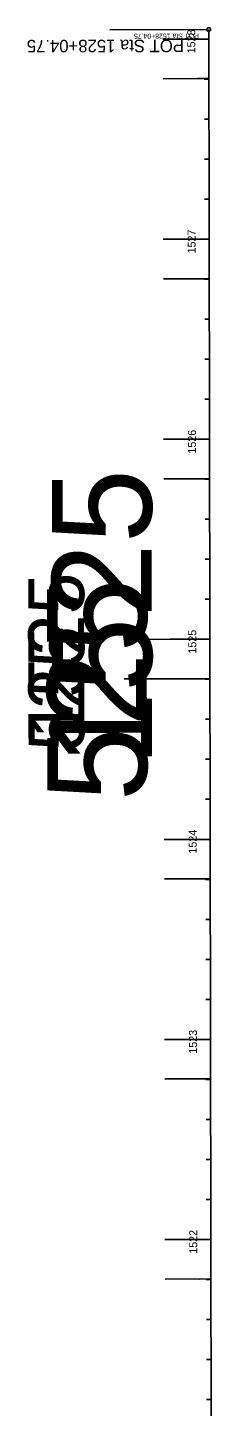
# Model space of a CAD drawing. Extents: x 448091 to 665917, y 1461380 to 1587607.
# Drawn here: x 450278 to 450373, y 1506458 to 1507147 of the extents above; entities that cross this region are included whole.
import ezdxf

# ---------------------------------------------------------------- set-up
doc = ezdxf.new("R2010")
doc.units = 0
for name, color, linetype in [('AttenuatorTM', 7, 'Continuous'), ('ATVHP', 7, 'Continuous'), ('Default', 7, 'Continuous'), ('TextShtNo', 7, 'Continuous'), ('TextTitle', 7, 'Continuous')]:
    doc.layers.add(name, color=color, linetype=linetype)

msp = doc.modelspace()

# ---------------------------------------------------------------- linework, layer by layer
at = {"layer": 'ATVHP'}
for p, q in [((450373.15, 1504839.62), (450369.29, 1507146.05)), ((450369.33, 1507121.54), (450363.58, 1507121.53)), ((450369.5, 1507021.54), (450363.75, 1507021.53)), ((450369.67, 1506921.54), (450363.92, 1506921.53)), ((450369.83, 1506821.54), (450349.08, 1506821.51)), ((450370, 1506721.54), (450364.25, 1506721.53)), ((450370.17, 1506621.54), (450364.42, 1506621.53)), ((450370.34, 1506521.54), (450364.59, 1506521.53))]:
    msp.add_line(p, q, dxfattribs=at)
at = {"layer": 'Default'}
for p, q in [((450368.29, 1507146.05), (450319.69, 1507145.97)), ((450369.3, 1507141.3), (450346.3, 1507141.26)), ((450369.3, 1507141.3), (450365, 1507141.29)), ((450369.33, 1507121.54), (450346.33, 1507121.5)), ((450369.33, 1507121.3), (450367.03, 1507121.3)), ((450369.37, 1507101.3), (450367.07, 1507101.3)), ((450369.4, 1507081.3), (450367.1, 1507081.3)), ((450369.43, 1507061.3), (450367.13, 1507061.3)), ((450369.47, 1507041.3), (450346.47, 1507041.26)), ((450369.47, 1507041.3), (450365.17, 1507041.29)), ((450369.5, 1507021.54), (450346.5, 1507021.5)), ((450369.5, 1507021.3), (450367.2, 1507021.3)), ((450369.53, 1507001.3), (450367.23, 1507001.3)), ((450369.57, 1506981.3), (450367.27, 1506981.3)), ((450369.6, 1506961.3), (450367.3, 1506961.3)), ((450369.63, 1506941.3), (450346.63, 1506941.26)), ((450369.63, 1506941.3), (450365.33, 1506941.29)), ((450369.67, 1506921.54), (450346.67, 1506921.5)), ((450369.67, 1506921.3), (450367.37, 1506921.3)), ((450369.7, 1506901.3), (450367.4, 1506901.3)), ((450369.73, 1506881.3), (450367.43, 1506881.3)), ((450369.77, 1506861.3), (450367.47, 1506861.3)), ((450369.8, 1506841.3), (450326.8, 1506841.23)), ((450369.8, 1506841.3), (450365.5, 1506841.29)), ((450369.83, 1506821.54), (450326.83, 1506821.47)), ((450369.83, 1506821.3), (450367.53, 1506821.3)), ((450369.87, 1506801.3), (450367.57, 1506801.3)), ((450369.9, 1506781.3), (450367.6, 1506781.3)), ((450369.93, 1506761.3), (450367.63, 1506761.3)), ((450369.97, 1506741.3), (450346.97, 1506741.26)), ((450369.97, 1506741.3), (450365.67, 1506741.29)), ((450370, 1506721.54), (450347, 1506721.5)), ((450370, 1506721.3), (450367.7, 1506721.3)), ((450370.03, 1506701.3), (450367.73, 1506701.3)), ((450370.07, 1506681.3), (450367.77, 1506681.3)), ((450370.1, 1506661.3), (450367.8, 1506661.3)), ((450370.14, 1506641.3), (450347.14, 1506641.26)), ((450370.14, 1506641.3), (450365.84, 1506641.3)), ((450370.17, 1506621.54), (450347.17, 1506621.51)), ((450370.17, 1506621.3), (450367.87, 1506621.3)), ((450370.2, 1506601.3), (450367.9, 1506601.3)), ((450370.24, 1506581.3), (450367.94, 1506581.3)), ((450370.27, 1506561.3), (450367.97, 1506561.3)), ((450370.3, 1506541.3), (450347.3, 1506541.26)), ((450370.3, 1506541.3), (450366, 1506541.3)), ((450370.34, 1506521.54), (450347.34, 1506521.51)), ((450370.34, 1506521.3), (450368.04, 1506521.3)), ((450370.37, 1506501.3), (450368.07, 1506501.3)), ((450370.4, 1506481.3), (450368.1, 1506481.3)), ((450370.44, 1506461.3), (450368.14, 1506461.3))]:
    msp.add_line(p, q, dxfattribs=at)
msp.add_circle((450369.29, 1507146.05), 1, dxfattribs=at)
at = {"layer": 'TextShtNo'}
msp.add_line((450371.97, 1505546.64), (450369.29, 1507146.05), dxfattribs=at)
at = {"layer": 'TextTitle'}
for p, q in [((450369.3, 1507141.3), (450359.3, 1507141.28)), ((450369.47, 1507041.3), (450359.47, 1507041.28)), ((450369.63, 1506941.3), (450359.63, 1506941.29)), ((450369.8, 1506841.3), (450349.8, 1506841.27)), ((450369.97, 1506741.3), (450359.97, 1506741.29)), ((450370.14, 1506641.3), (450360.14, 1506641.29)), ((450370.3, 1506541.3), (450360.3, 1506541.29))]:
    msp.add_line(p, q, dxfattribs=at)

# ---------------------------------------------------------------- texts
at = {"layer": 'AttenuatorTM'}
msp.add_text('POT Sta 1528+04.75', height=6.25, rotation=180.09585, dxfattribs=at).set_placement((450356.8, 1507141.03))
at = {"layer": 'ATVHP'}
msp.add_text('525', height=50, rotation=90.09585, dxfattribs=at).set_placement((450338.3, 1506760.3))
at = {"layer": 'Default'}
for s, height, rotation, p in [('1528', 4, 90.09585, (450362.51, 1507134.19)), ('POT Sta 1528+04.75', 2.5, 180.09585, (450364.29, 1507144.04)), ('1527', 4, 90.09585, (450362.68, 1507034.16)), ('1526', 4, 90.09585, (450362.85, 1506934.11)), ('1525', 28, 90.09585, (450306.88, 1506791.26)), ('525', 28, 90.09585, (450306.89, 1506785.39)), ('1525', 4, 90.09585, (450363.01, 1506834.16)), ('1524', 4, 90.09585, (450363.18, 1506734.17)), ('1523', 4, 90.09585, (450363.35, 1506634.17)), ('1522', 4, 90.09585, (450363.51, 1506534.17))]:
    msp.add_text(s, height=height, rotation=rotation, dxfattribs=at).set_placement(p)
at = {"layer": 'TextTitle'}
msp.add_text('1525', height=50, rotation=90.09585, dxfattribs=at).set_placement((450340.82, 1506777.75))

doc.saveas('drawing.dxf')
